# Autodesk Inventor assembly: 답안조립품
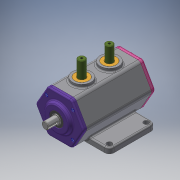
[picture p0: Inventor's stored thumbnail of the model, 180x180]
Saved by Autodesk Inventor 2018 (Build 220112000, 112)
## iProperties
Created: 2021-06
Part Number: 답안조립품
Document SubType Name: Assembly
Designer: 1class 18
Author: 1class 18
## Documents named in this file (11)
- C:\Users\1class 18\Desktop\710606V1041\답안조립품.iam
- C:\Users\1class 18\Desktop\710606V1041\부품1.ipt
- C:\Users\1class 18\Desktop\710606V1041\편심축.ipt
- C:\Users\1class 18\Desktop\710606V1041\베어링 6302.ipt
- C:\Users\1class 18\Desktop\710606V1041\베어링 6203.ipt
- C:\Users\1class 18\Desktop\710606V1041\오일실.ipt
- C:\Users\1class 18\Desktop\710606V1041\앞커버.ipt
- C:\Users\1class 18\Desktop\710606V1041\뒷커버.ipt
- C:\Users\1class 18\Desktop\710606V1041\볼트 M4.ipt
- C:\Users\1class 18\Desktop\710606V1041\부시.ipt
- C:\Users\1class 18\Desktop\710606V1041\슬라이더.ipt
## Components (10 placed, 3 different names)
1. 7-베어링 6203:1
2. 9-M4-소켓머리:1
3. 9-M4-소켓머리:2
4. 9-M4-소켓머리:4
5. 9-M4-소켓머리:5
6. 9-M4-소켓머리:6
7. 9-M4-소켓머리:7
8. 9-M4-소켓머리:8
9. 9-M4-소켓머리:9
10. 8-오일실:2
